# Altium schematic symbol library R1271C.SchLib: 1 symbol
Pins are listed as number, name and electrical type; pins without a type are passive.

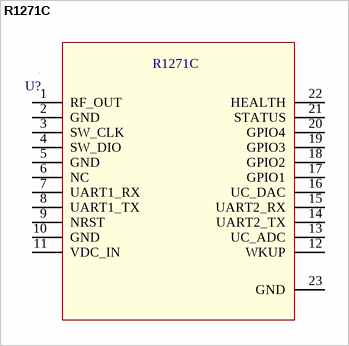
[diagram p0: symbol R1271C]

## R1271C
designator U?  (value not drawn)
pins: 1 RF_OUT, 2 GND, 3 SW_CLK, 4 SW_DIO, 5 GND, 6 NC, 7 UART1_RX, 8 UART1_TX, 9 NRST, 10 GND, 11 VDC_IN, 12 WKUP, 13 UC_ADC, 14 UART2_TX, 15 UART2_RX, 16 UC_DAC, 17 GPIO1, 18 GPIO2, 19 GPIO3, 20 GPIO4, 21 STATUS, 22 HEALTH, 23 GND (power)
1 alternate drawing of the same symbol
